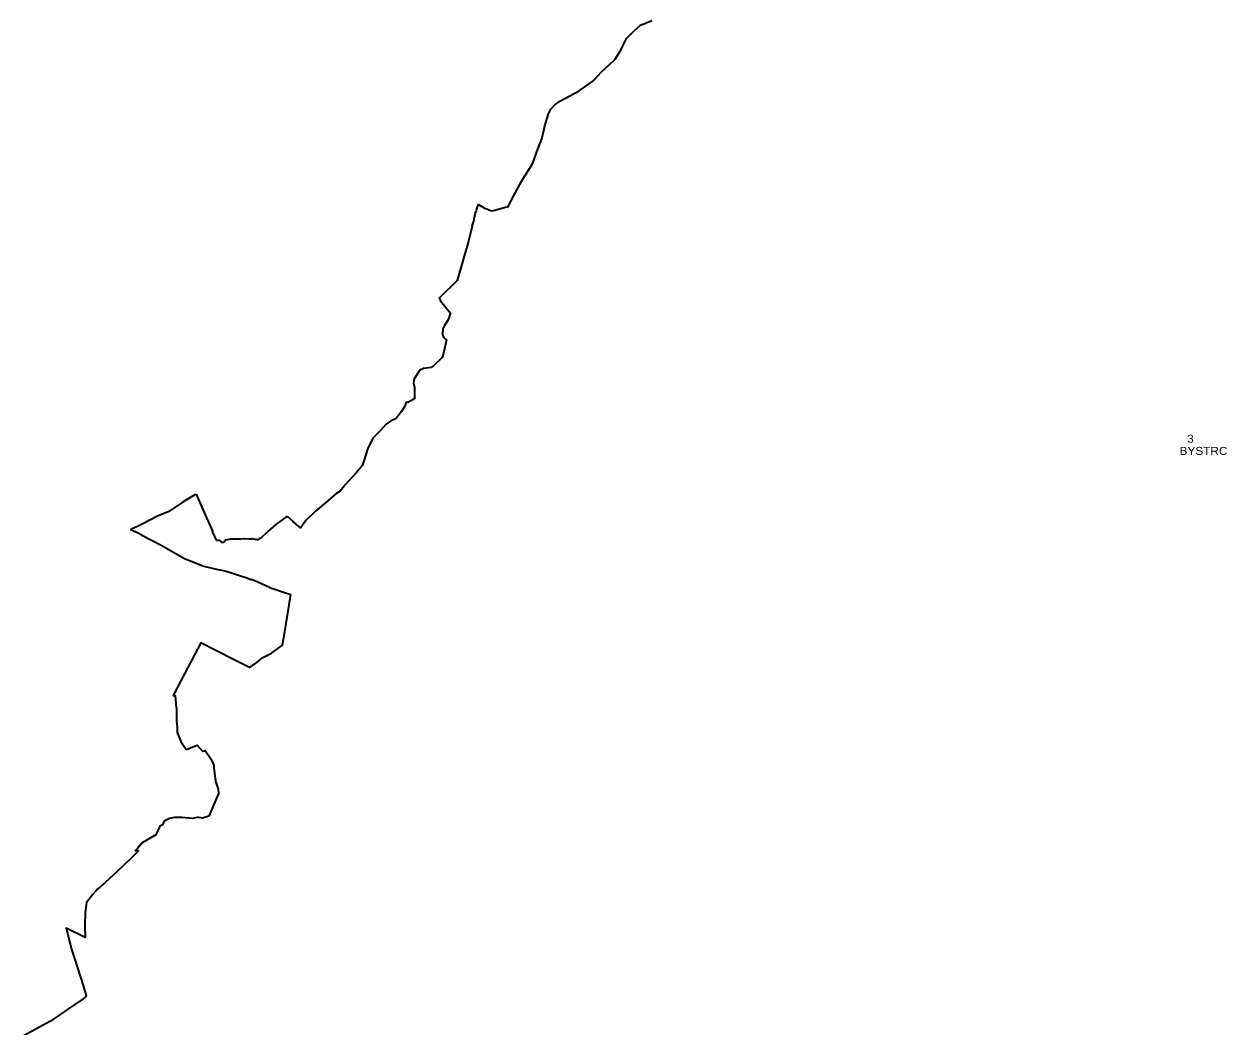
# Model space of a CAD drawing. Extents: x -610940 to -588976, y -1170376 to -1149800.
# Drawn here: x -610711 to -606953, y -1156549 to -1153413 of the extents above; entities that cross this region are included whole.
import ezdxf

# ---------------------------------------------------------------- set-up
doc = ezdxf.new("R2010")
doc.units = 0
doc.header["$LTSCALE"] = 10
doc.layers.add('54', color=7, linetype='Continuous', lineweight=35)
doc.layers.add('55', color=7, linetype='Continuous')
doc.layers.add('56', color=7, linetype='Continuous')

msp = doc.modelspace()

# ---------------------------------------------------------------- linework, layer by layer
at = {"layer": '54'}
for p, q in [((-608782.26, -1153415.53), (-608750, -1153402.27)), ((-609035.03, -1153653.83), (-608977.49, -1153622.29)), ((-609300.62, -1154003.82), (-609299.68, -1154000)), ((-609299.09, -1153997.61), (-609299.68, -1154000)), ((-609272.89, -1153988.86), (-609269.57, -1153990.05)), ((-609249.71, -1153997.14), (-609244.32, -1153995.75)), ((-609244.32, -1153995.75), (-609203.61, -1153985.18)), ((-609203.61, -1153985.18), (-609200.62, -1153986.61)), ((-609200.62, -1153986.61), (-609197.16, -1153979.74)), ((-610342.37, -1154975.76), (-610294.56, -1154950.66)), ((-610294.56, -1154950.66), (-610256.3, -1154935.18)), ((-610376.63, -1154992.65), (-610342.37, -1154975.76)), ((-609925.12, -1154977.54), (-609949.84, -1155000)), ((-609889.86, -1154951.95), (-609925.12, -1154977.54)), ((-610378.54, -1154993.58), (-610376.63, -1154992.65)), ((-610378.54, -1154993.58), (-610365.02, -1155000)), ((-610363.12, -1155000.9), (-610365.02, -1155000)), ((-610342.92, -1155011.4), (-610363.12, -1155000.9)), ((-610122.9, -1154998.65), (-610122.27, -1155000)), ((-610109.63, -1155027.03), (-610122.27, -1155000)), ((-610007.64, -1155022.56), (-610000, -1155022.94)), ((-609999.01, -1155022.99), (-610000, -1155022.94)), ((-609983.27, -1155025.56), (-609999.01, -1155022.99)), ((-609950.85, -1155000.92), (-609949.84, -1155000)), ((-610002.36, -1155149.6), (-610000, -1155150.38)), ((-609998.72, -1155150.81), (-610000, -1155150.38)), ((-609944.42, -1155174.64), (-609924.82, -1155181.31)), ((-610007.71, -1155424.72), (-610000, -1155419.95)), ((-609991.44, -1155414.65), (-610000, -1155419.95)), ((-610357, -1156000.94), (-610355.86, -1156000)), ((-610352.53, -1155997.25), (-610355.86, -1156000))]:
    msp.add_line(p, q, dxfattribs=at)
for points in [[(-608977.49, -1153622.29), (-608934.07, -1153591.76), (-608926.83, -1153584.89), (-608907.85, -1153563.59), (-608867.5, -1153525.82), (-608864.4, -1153522.73), (-608846.96, -1153494.42), (-608839.57, -1153479.33), (-608829.5, -1153458.45), (-608806.73, -1153435.1)], [(-608782.26, -1153415.53), (-608786.24, -1153418.14), (-608806.73, -1153435.1)], [(-609197.16, -1153979.74), (-609181.96, -1153951.89), (-609156.04, -1153903.42), (-609121.85, -1153848.43), (-609109.38, -1153812.67), (-609094.14, -1153771.75), (-609086.51, -1153742.16), (-609084.42, -1153731.84), (-609072.98, -1153694.35), (-609065.83, -1153679.01), (-609052.61, -1153666.18), (-609035.03, -1153653.83)], [(-609310.9, -1154045.08), (-609307.66, -1154032.22), (-609305.39, -1154023.22), (-609303.77, -1154016.7), (-609302.15, -1154010.09), (-609300.62, -1154003.82)], [(-609295.01, -1153981.23), (-609295.85, -1153984.62), (-609297.66, -1153991.85), (-609299.09, -1153997.61)], [(-609272.89, -1153988.86), (-609292.64, -1153977.47), (-609295.01, -1153981.23)], [(-609269.57, -1153990.05), (-609265.94, -1153991.34), (-609258.88, -1153993.86), (-609256.03, -1153994.88), (-609249.71, -1153997.14)], [(-609310.9, -1154045.08), (-609322.85, -1154092.15), (-609357.87, -1154215.27), (-609414.09, -1154269.98), (-609410.18, -1154278.86), (-609379.06, -1154317.23), (-609380.95, -1154322.26), (-609386.26, -1154338.26), (-609398.28, -1154355.3), (-609403.34, -1154366.09), (-609404.07, -1154384.12), (-609400.89, -1154392.11), (-609391.75, -1154400.5), (-609400.44, -1154442.02), (-609405.12, -1154455.36), (-609431.71, -1154481.8), (-609439.06, -1154487.52), (-609463.78, -1154490.22), (-609475.32, -1154495.44), (-609492.4, -1154522.64), (-609494.91, -1154535.97), (-609491.22, -1154548.41), (-609491.55, -1154584.86), (-609512.71, -1154596.57), (-609517.53, -1154595.68), (-609521.63, -1154607.68), (-609526.63, -1154616.77), (-609532.5, -1154625.14), (-609542.52, -1154638.22), (-609548.28, -1154646.13), (-609566.14, -1154655.04), (-609580.46, -1154663.82), (-609598.34, -1154685.42), (-609621.3, -1154707.59), (-609627.04, -1154719.01), (-609637.29, -1154739.32), (-609645.24, -1154765.86), (-609655.16, -1154794.07), (-609673.28, -1154816.46), (-609706.93, -1154852.9)], [(-609706.93, -1154852.9), (-609723.63, -1154873.35), (-609737.01, -1154882.38), (-609762.43, -1154903.82), (-609800.85, -1154936.33), (-609831.01, -1154965.07), (-609847.4, -1154989.85)], [(-610203.12, -1154899.44), (-610214.4, -1154907.02), (-610256.3, -1154935.18)], [(-610203.12, -1154899.44), (-610176.45, -1154884.61), (-610174.1, -1154883.29)], [(-610174.1, -1154883.29), (-610148.81, -1154940.01), (-610122.9, -1154998.65)], [(-609889.86, -1154951.95), (-609872.12, -1154967.79), (-609869.5, -1154970.13), (-609847.4, -1154989.85)], [(-610342.92, -1155011.4), (-610281.2, -1155043.11), (-610212.5, -1155083.1)], [(-610094.3, -1155033.25), (-610091.04, -1155033.31), (-610087.2, -1155033.39), (-610086.33, -1155032.13), (-610081.81, -1155025.56)], [(-610081.81, -1155025.56), (-610064.29, -1155022.68), (-610044.68, -1155022.89), (-610035.02, -1155023.04), (-610023.68, -1155021.39), (-610009.59, -1155022.35), (-610007.64, -1155022.56)], [(-609983.27, -1155025.56), (-609969.99, -1155018.59), (-609950.85, -1155000.92)], [(-610109.63, -1155027.03), (-610102.12, -1155027.19), (-610094.3, -1155033.25)], [(-610212.5, -1155083.1), (-610204.49, -1155086.31), (-610154.45, -1155106.34), (-610149.75, -1155108.22), (-610105.78, -1155118.26), (-610098.94, -1155119.83), (-610080.32, -1155124.08), (-610057.27, -1155131.21), (-610041.73, -1155136.01)], [(-610041.73, -1155136.01), (-610015.16, -1155145.18), (-610002.36, -1155149.6)], [(-609944.42, -1155174.64), (-609980.81, -1155158.67), (-609998.72, -1155150.81)], [(-609991.44, -1155414.65), (-609984.3, -1155409.87), (-609965.78, -1155393.59), (-609938.78, -1155380.7), (-609904.32, -1155355.16), (-609904.04, -1155353.09), (-609897.69, -1155319.9), (-609878.39, -1155197.12)], [(-609924.82, -1155181.31), (-609903.65, -1155188.52), (-609878.39, -1155197.12)], [(-610007.71, -1155424.72), (-610008.56, -1155424.28), (-610013.76, -1155421.61), (-610025.35, -1155415.68), (-610052.74, -1155402.05), (-610114.75, -1155370.7), (-610159.53, -1155348.28), (-610208.88, -1155442.99), (-610245.25, -1155512.93), (-610239.52, -1155512.5), (-610237.07, -1155538.16), (-610236.73, -1155541.74), (-610235.53, -1155554.1), (-610235.19, -1155557.76), (-610234.7, -1155562.96), (-610234.73, -1155593.51), (-610232.51, -1155609.77), (-610232.58, -1155615.55), (-610232.72, -1155628.04), (-610221.29, -1155656.27), (-610204.96, -1155680.94), (-610170.7, -1155667.35), (-610153.72, -1155686.57), (-610148.95, -1155685.15), (-610145.74, -1155684.18), (-610127.84, -1155710.5), (-610118.79, -1155730.86), (-610118.22, -1155735.75), (-610117.95, -1155738.04), (-610112.91, -1155780.54), (-610104.99, -1155805.63), (-610104.25, -1155819.46), (-610134.1, -1155889.48), (-610154.37, -1155895.6), (-610163.82, -1155894.5), (-610170.36, -1155893.74), (-610185.37, -1155897.4), (-610217.06, -1155894.22), (-610241.4, -1155894.38), (-610256.76, -1155897.62)], [(-610256.76, -1155897.62), (-610273.92, -1155905.93), (-610279, -1155917.14), (-610287.29, -1155921.17), (-610298.73, -1155946.62), (-610299.25, -1155947.78), (-610342.79, -1155972.79), (-610357.16, -1155990.78), (-610360.5, -1155993.94), (-610364.01, -1155997.25), (-610352.53, -1155997.25)], [(-610357, -1156000.94), (-610374.75, -1156018.72), (-610420.8, -1156062.61), (-610458.3, -1156097.07), (-610481.46, -1156118.17), (-610488.2, -1156125.06), (-610497.05, -1156135.61), (-610507.72, -1156148.83), (-610511.65, -1156154.32), (-610515.86, -1156159.24), (-610520.44, -1156190.87), (-610521.16, -1156233.13), (-610520.05, -1156269.6), (-610579.57, -1156239.84), (-610562.89, -1156306), (-610526.88, -1156419.36), (-610516.89, -1156451.91), (-610518.54, -1156453.65), (-610521.01, -1156456.31), (-610526.68, -1156460.99), (-610604.67, -1156514.35), (-610628.38, -1156530.31), (-610711.4, -1156575.52)]]:
    msp.add_lwpolyline(points, dxfattribs=at)

# ---------------------------------------------------------------- texts
at = {"layer": '55', "width": 1.1}
msp.add_text('BYSTRC ', height=25, dxfattribs=at).set_placement((-607100.9, -1154760.35))
at = {"layer": '56', "width": 1.1}
msp.add_text('3 ', height=25, dxfattribs=at).set_placement((-607077.31, -1154722.14))

doc.saveas('drawing.dxf')
